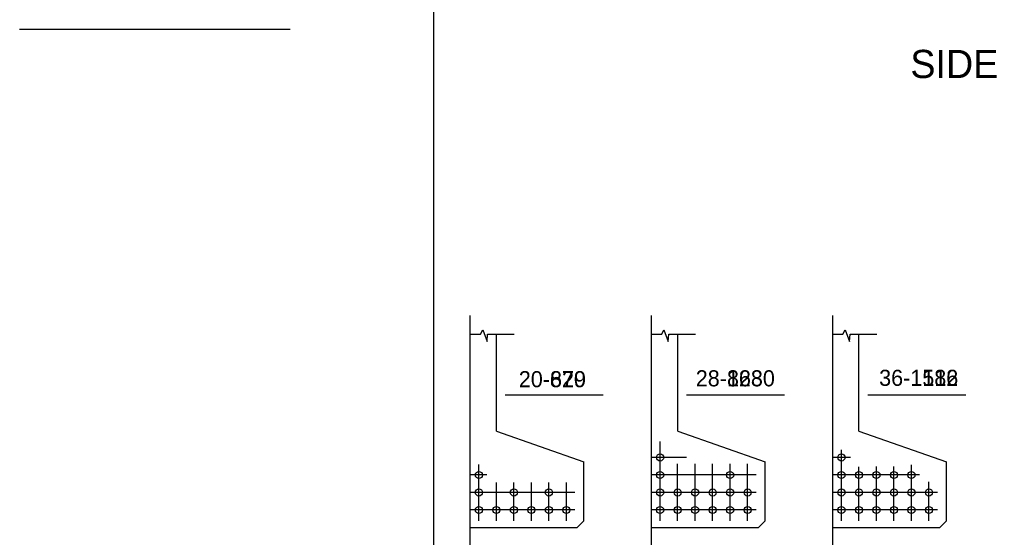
# Model space of a CAD drawing. Extents: x 1005 to 1133, y 2006 to 2074.
# Drawn here: x 1005.19 to 1025.34, y 2030.05 to 2040.77 of the extents above; entities that cross this region are included whole.
import ezdxf

# ---------------------------------------------------------------- set-up
doc = ezdxf.new("R2010")
doc.units = 0
for name, color, linetype in [('Level 1', 7, 'Continuous'), ('Level 2', 7, 'Continuous'), ('Level 37', 7, 'Continuous'), ('Level 8', 7, 'Continuous'), ('Level 9', 7, 'Continuous')]:
    doc.layers.add(name, color=color, linetype=linetype)

msp = doc.modelspace()

# ---------------------------------------------------------------- linework, layer by layer
at = {"layer": 'Level 1'}
msp.add_line((1013.763, 2012.562), (1013.763, 2068.561), dxfattribs=at)
at = {"layer": 'Level 37'}
msp.add_line((1010.791, 2040.561), (1005.193, 2040.561), dxfattribs=at)
at = {"layer": 'Level 8'}
for p, q in [((1014.516, 2014.747), (1014.516, 2034.639)), ((1018.266, 2014.747), (1018.266, 2034.639)), ((1022.016, 2014.747), (1022.016, 2034.639)), ((1014.729, 2034.258), (1014.776, 2034.347)), ((1014.776, 2034.347), (1014.865, 2034.104)), ((1018.479, 2034.258), (1018.526, 2034.347)), ((1018.526, 2034.347), (1018.615, 2034.104)), ((1022.229, 2034.258), (1022.276, 2034.347)), ((1022.276, 2034.347), (1022.365, 2034.104)), ((1014.516, 2034.258), (1014.729, 2034.258)), ((1014.865, 2034.104), (1014.878, 2034.258)), ((1014.878, 2034.258), (1015.427, 2034.258)), ((1015.06, 2032.248), (1015.06, 2034.258)), ((1018.266, 2034.258), (1018.479, 2034.258)), ((1018.615, 2034.104), (1018.628, 2034.258)), ((1018.628, 2034.258), (1019.177, 2034.258)), ((1018.81, 2032.248), (1018.81, 2034.258)), ((1022.016, 2034.258), (1022.229, 2034.258)), ((1022.365, 2034.104), (1022.378, 2034.258)), ((1022.378, 2034.258), (1022.927, 2034.258)), ((1022.56, 2032.248), (1022.56, 2034.258)), ((1015.244, 2032.998), (1017.269, 2032.998)), ((1018.994, 2032.998), (1021.019, 2032.998)), ((1022.744, 2032.998), (1024.769, 2032.998)), ((1015.06, 2032.248), (1016.869, 2031.614)), ((1018.81, 2032.248), (1020.619, 2031.614)), ((1022.56, 2032.248), (1024.369, 2031.614)), ((1018.447, 2030.392), (1018.447, 2032.035)), ((1018.994, 2031.704), (1018.266, 2031.704)), ((1022.383, 2031.704), (1022.016, 2031.704)), ((1022.197, 2030.392), (1022.197, 2031.859)), ((1014.697, 2030.392), (1014.697, 2031.558)), ((1016.869, 2030.392), (1016.869, 2031.614)), ((1018.809, 2030.392), (1018.809, 2031.576)), ((1019.171, 2030.392), (1019.171, 2031.576)), ((1019.533, 2030.392), (1019.533, 2031.576)), ((1019.895, 2030.392), (1019.895, 2031.576)), ((1020.257, 2030.392), (1020.257, 2031.576)), ((1020.619, 2030.392), (1020.619, 2031.614)), ((1022.559, 2030.392), (1022.559, 2031.512)), ((1022.921, 2030.392), (1022.921, 2031.516)), ((1023.283, 2030.392), (1023.283, 2031.52)), ((1023.645, 2030.392), (1023.645, 2031.55)), ((1024.369, 2030.392), (1024.369, 2031.614)), ((1014.858, 2031.342), (1014.516, 2031.342)), ((1020.431, 2031.342), (1018.266, 2031.342)), ((1023.811, 2031.342), (1022.016, 2031.342)), ((1015.059, 2030.392), (1015.059, 2031.188)), ((1015.421, 2030.392), (1015.421, 2031.188)), ((1015.783, 2030.392), (1015.783, 2031.188)), ((1016.145, 2030.392), (1016.145, 2031.188)), ((1016.507, 2030.392), (1016.507, 2031.188)), ((1024.007, 2030.392), (1024.007, 2031.201)), ((1016.681, 2030.98), (1014.516, 2030.98)), ((1020.431, 2030.98), (1018.266, 2030.98)), ((1024.181, 2030.98), (1022.016, 2030.98)), ((1016.681, 2030.618), (1014.516, 2030.618)), ((1020.431, 2030.618), (1018.266, 2030.618)), ((1024.181, 2030.618), (1022.016, 2030.618)), ((1016.733, 2030.256), (1016.869, 2030.392)), ((1020.483, 2030.256), (1020.619, 2030.392)), ((1024.233, 2030.256), (1024.369, 2030.392)), ((1014.516, 2030.256), (1016.733, 2030.256)), ((1018.266, 2030.256), (1020.483, 2030.256)), ((1022.016, 2030.256), (1024.233, 2030.256))]:
    msp.add_line(p, q, dxfattribs=at)
for centre in [(1018.447, 2031.704), (1022.197, 2031.704), (1014.697, 2031.342), (1018.447, 2031.342), (1022.197, 2031.342), (1022.559, 2031.342), (1022.921, 2031.342), (1023.283, 2031.342), (1023.645, 2031.342), (1014.697, 2030.98), (1015.421, 2030.98), (1016.145, 2030.98), (1018.447, 2030.98), (1018.809, 2030.98), (1019.171, 2030.98), (1019.533, 2030.98), (1019.895, 2030.98), (1020.257, 2030.98), (1022.197, 2030.98), (1022.559, 2030.98), (1022.921, 2030.98), (1023.283, 2030.98), (1023.645, 2030.98), (1024.007, 2030.98), (1014.697, 2030.618), (1015.059, 2030.618), (1015.421, 2030.618), (1015.783, 2030.618), (1016.145, 2030.618), (1016.507, 2030.618), (1018.447, 2030.618), (1018.809, 2030.618), (1019.171, 2030.618), (1019.533, 2030.618), (1019.895, 2030.618), (1020.257, 2030.618), (1022.197, 2030.618), (1022.559, 2030.618), (1022.921, 2030.618), (1023.283, 2030.618), (1023.645, 2030.618), (1024.007, 2030.618)]:
    msp.add_circle(centre, 0.073, dxfattribs=at)
at = {"layer": 'Level 9'}
for p, q in [((1014.516, 2014.747), (1014.516, 2034.639)), ((1018.266, 2014.747), (1018.266, 2034.639)), ((1022.016, 2014.747), (1022.016, 2034.639)), ((1014.729, 2034.258), (1014.776, 2034.347)), ((1014.776, 2034.347), (1014.865, 2034.104)), ((1018.479, 2034.258), (1018.526, 2034.347)), ((1018.526, 2034.347), (1018.615, 2034.104)), ((1022.229, 2034.258), (1022.276, 2034.347)), ((1022.276, 2034.347), (1022.365, 2034.104)), ((1014.516, 2034.258), (1014.729, 2034.258)), ((1014.865, 2034.104), (1014.878, 2034.258)), ((1014.878, 2034.258), (1015.427, 2034.258)), ((1015.06, 2032.248), (1015.06, 2034.258)), ((1018.266, 2034.258), (1018.479, 2034.258)), ((1018.615, 2034.104), (1018.628, 2034.258)), ((1018.628, 2034.258), (1019.177, 2034.258)), ((1018.81, 2032.248), (1018.81, 2034.258)), ((1022.016, 2034.258), (1022.229, 2034.258)), ((1022.365, 2034.104), (1022.378, 2034.258)), ((1022.378, 2034.258), (1022.927, 2034.258)), ((1022.56, 2032.248), (1022.56, 2034.258)), ((1015.244, 2032.998), (1017.269, 2032.998)), ((1018.994, 2032.998), (1021.019, 2032.998)), ((1022.744, 2032.998), (1024.769, 2032.998)), ((1015.06, 2032.248), (1016.869, 2031.614)), ((1018.81, 2032.248), (1020.619, 2031.614)), ((1022.56, 2032.248), (1024.369, 2031.614)), ((1022.383, 2031.704), (1022.016, 2031.704)), ((1022.197, 2030.392), (1022.197, 2031.859)), ((1014.697, 2030.392), (1014.697, 2031.558)), ((1016.869, 2030.392), (1016.869, 2031.614)), ((1018.447, 2030.392), (1018.447, 2031.576)), ((1018.809, 2030.392), (1018.809, 2031.576)), ((1019.171, 2030.392), (1019.171, 2031.576)), ((1019.533, 2030.392), (1019.533, 2031.576)), ((1019.895, 2030.392), (1019.895, 2031.576)), ((1020.257, 2030.392), (1020.257, 2031.576)), ((1020.619, 2030.392), (1020.619, 2031.614)), ((1022.559, 2030.392), (1022.559, 2031.512)), ((1022.921, 2030.392), (1022.921, 2031.516)), ((1023.283, 2030.392), (1023.283, 2031.52)), ((1023.645, 2030.392), (1023.645, 2031.55)), ((1024.369, 2030.392), (1024.369, 2031.614)), ((1014.858, 2031.342), (1014.516, 2031.342)), ((1020.431, 2031.342), (1018.266, 2031.342)), ((1023.811, 2031.342), (1022.016, 2031.342)), ((1015.059, 2030.392), (1015.059, 2031.188)), ((1015.421, 2030.392), (1015.421, 2031.188)), ((1015.783, 2030.392), (1015.783, 2031.188)), ((1016.145, 2030.392), (1016.145, 2031.188)), ((1016.507, 2030.392), (1016.507, 2031.188)), ((1024.007, 2030.392), (1024.007, 2031.201)), ((1016.681, 2030.98), (1014.516, 2030.98)), ((1020.431, 2030.98), (1018.266, 2030.98)), ((1024.181, 2030.98), (1022.016, 2030.98)), ((1016.681, 2030.618), (1014.516, 2030.618)), ((1020.431, 2030.618), (1018.266, 2030.618)), ((1024.181, 2030.618), (1022.016, 2030.618)), ((1016.733, 2030.256), (1016.869, 2030.392)), ((1020.483, 2030.256), (1020.619, 2030.392)), ((1024.233, 2030.256), (1024.369, 2030.392)), ((1014.516, 2030.256), (1016.733, 2030.256)), ((1018.266, 2030.256), (1020.483, 2030.256)), ((1022.016, 2030.256), (1024.233, 2030.256))]:
    msp.add_line(p, q, dxfattribs=at)
for centre in [(1022.197, 2031.704), (1014.697, 2031.342), (1018.447, 2031.342), (1019.895, 2031.342), (1022.197, 2031.342), (1022.559, 2031.342), (1022.921, 2031.342), (1023.283, 2031.342), (1023.645, 2031.342), (1014.697, 2030.98), (1015.421, 2030.98), (1016.145, 2030.98), (1018.447, 2030.98), (1018.809, 2030.98), (1019.171, 2030.98), (1019.533, 2030.98), (1019.895, 2030.98), (1020.257, 2030.98), (1022.197, 2030.98), (1022.559, 2030.98), (1022.921, 2030.98), (1023.283, 2030.98), (1023.645, 2030.98), (1024.007, 2030.98), (1014.697, 2030.618), (1015.059, 2030.618), (1015.421, 2030.618), (1015.783, 2030.618), (1016.145, 2030.618), (1016.507, 2030.618), (1018.447, 2030.618), (1018.809, 2030.618), (1019.171, 2030.618), (1019.533, 2030.618), (1019.895, 2030.618), (1020.257, 2030.618), (1022.197, 2030.618), (1022.559, 2030.618), (1022.921, 2030.618), (1023.283, 2030.618), (1023.645, 2030.618), (1024.007, 2030.618)]:
    msp.add_circle(centre, 0.073, dxfattribs=at)

# ---------------------------------------------------------------- texts
at = {"layer": 'Level 2'}
msp.add_text('             SIDE VIEW & TYPICAL SECTION IN SPAN', height=0.58333, dxfattribs=at).set_placement((1020.805, 2039.556))
at = {"layer": 'Level 8'}
for s, p in [('28-868', (1019.184, 2033.176)), ('36-1116', (1022.977, 2033.186)), ('20-620', (1015.523, 2033.158))]:
    msp.add_text(s, height=0.3333, dxfattribs=at).set_placement(p)
at = {"layer": 'Level 9'}
for s, p in [('28-1230', (1019.184, 2033.176)), ('36-1582', (1022.977, 2033.186)), ('20-879', (1015.523, 2033.158))]:
    msp.add_text(s, height=0.3333, dxfattribs=at).set_placement(p)

doc.saveas('drawing.dxf')
